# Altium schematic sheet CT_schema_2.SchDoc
size 276 x 169 mm
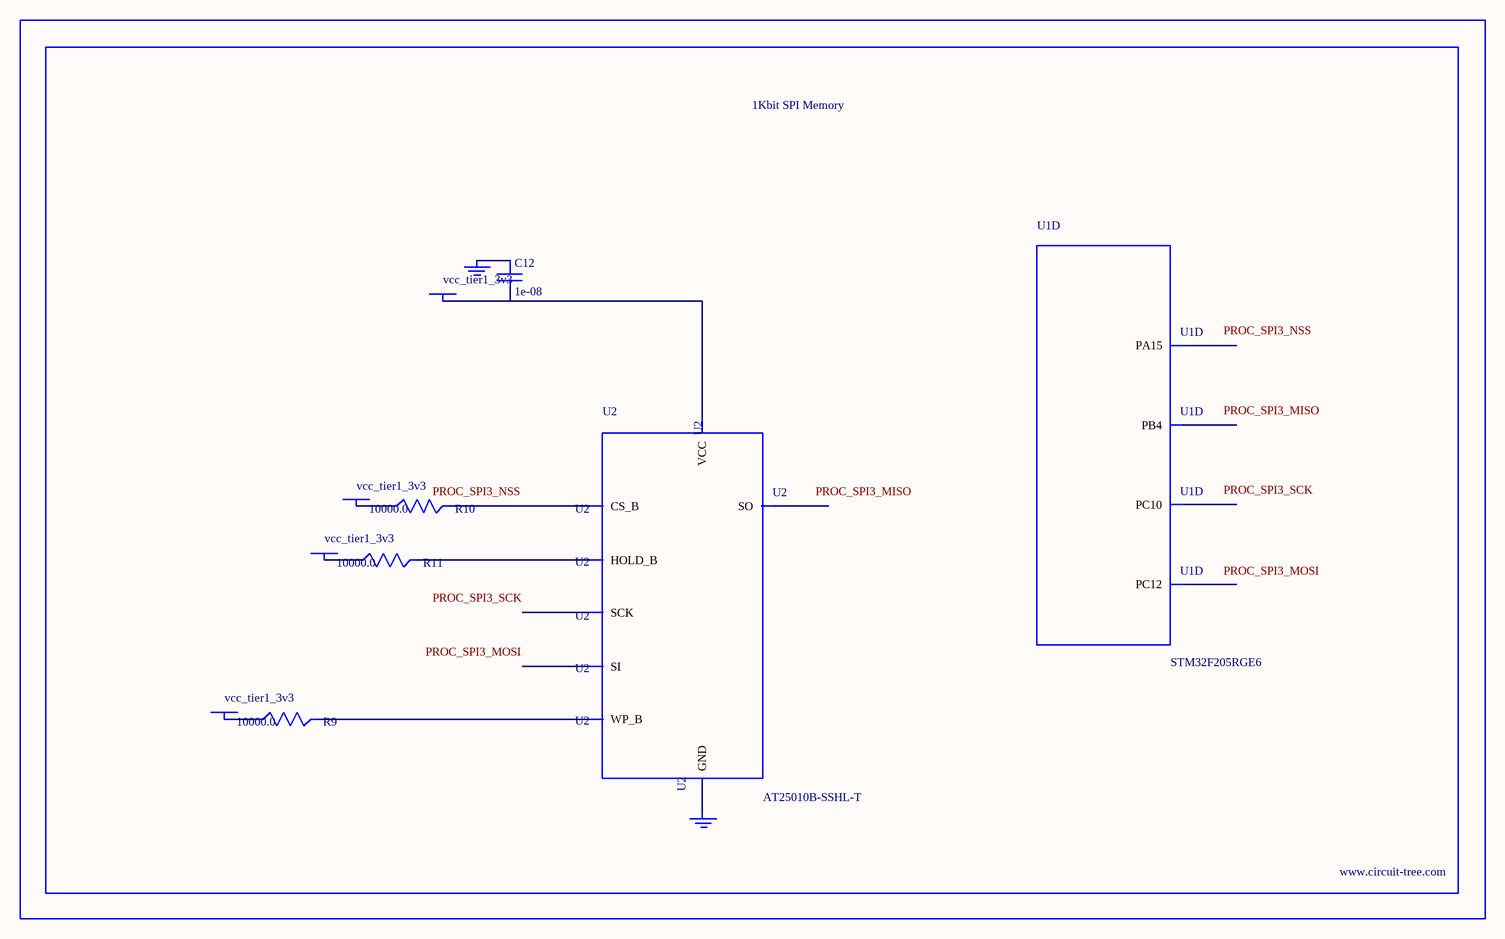
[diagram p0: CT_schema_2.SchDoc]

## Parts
BORDER1  (no value)
C12  1e-08  [C0402]
GND_INSTANCE_1_0  (no value)
GND_INSTANCE_1_1  (no value)
POWER_INSTANCE_1_0  vcc_tier1_3v3
POWER_INSTANCE_1_1  vcc_tier1_3v3
POWER_INSTANCE_1_2  vcc_tier1_3v3
POWER_INSTANCE_1_3  vcc_tier1_3v3
R9  10000.0  [R0603]
R10  10000.0  [R0603]
R11  10000.0  [R0603]
U1  STM32F205RGE6  [EWLCSP66]  (part D of 7)
U2  AT25010B-SSHL-T  [SOIC-8]

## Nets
NetC12_1: C12.1 GND_INSTANCE_1_0.0(GND)
NetC12_2: C12.2 POWER_INSTANCE_1_3.0(PWR) U2.8(VCC)
NetGND_INSTANCE_1_1_0: GND_INSTANCE_1_1.0(GND) U2.4(GND)
NetPOWER_INSTANCE_1_0_0: POWER_INSTANCE_1_0.0(PWR) R10.1
NetPOWER_INSTANCE_1_1_0: POWER_INSTANCE_1_1.0(PWR) R9.1
NetPOWER_INSTANCE_1_2_0: POWER_INSTANCE_1_2.0(PWR) R11.1
NetR9_2: R9.2 U2.3(WP_B)
NetR10_2: R10.2 U2.1(CS_B)
NetR11_2: R11.2 U2.7(HOLD_B)

Not connected (* = marked no-connect by the designer): U1 A2(PA15) A3(PC12) B3(PC10) B4(PB4); U2 2(SO) 5(SI) 6(SCK)

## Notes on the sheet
- Labels drawn without touching a wire or pin: PROC_SPI3_MISO, PROC_SPI3_MOSI, PROC_SPI3_NSS, PROC_SPI3_SCK

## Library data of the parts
BORDER1 = BORDER_PAGE1
C12 = C0402C103K3RAC
GND_INSTANCE_1_0 GND_INSTANCE_1_1 = GND
POWER_INSTANCE_1_0-POWER_INSTANCE_1_3 = PWR
R9-R11 = RC0603JR-0710KL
